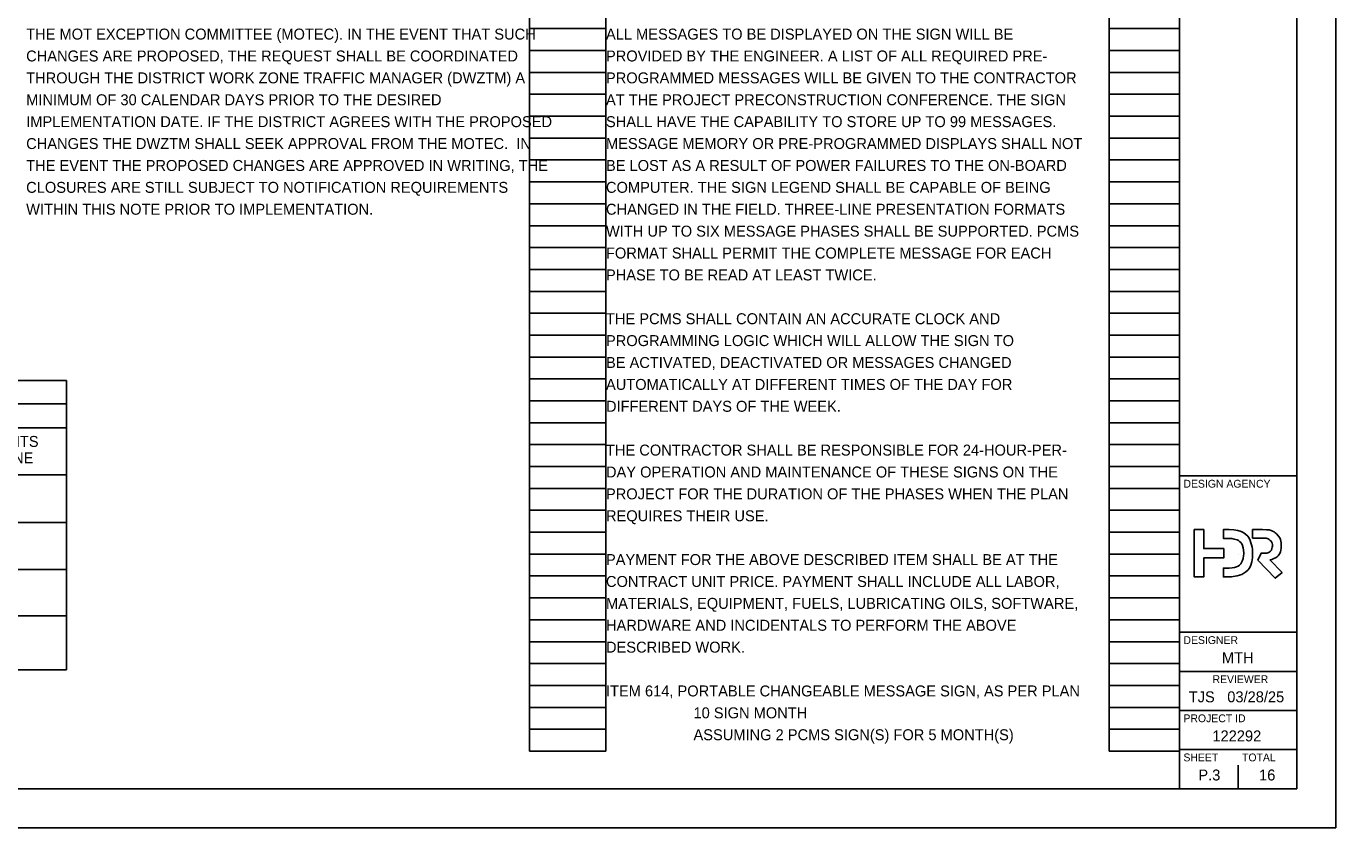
# Model space of a CAD drawing. Extents: x 0 to 49.3, y -31.9 to 22.
# Drawn here: x 17.24 to 34, y 0 to 10.25 of the extents above; entities that cross this region are included whole.
import ezdxf

# ---------------------------------------------------------------- set-up
doc = ezdxf.new("R2010")
doc.units = 0
for name, color, linetype in [('SH_Border', 7, 'Continuous'), ('SH_Cut_Line', 7, 'Continuous'), ('SH_Data', 7, 'Continuous'), ('SH_Text', 7, 'Continuous')]:
    doc.layers.add(name, color=color, linetype=linetype)

msp = doc.modelspace()

# ---------------------------------------------------------------- linework, layer by layer
at = {"layer": 'SH_Border'}
for p, q in [((32, 0.5), (32, 21.5)), ((32, 4.5), (33.5, 4.5)), ((32, 2.5), (33.5, 2.5)), ((32, 2), (33.5, 2)), ((32, 1.5), (33.5, 1.5)), ((32, 1), (33.5, 1))]:
    msp.add_line(p, q, dxfattribs=at)
msp.add_lwpolyline([(1.5, 21.5), (33.5, 21.5), (33.5, 0.5), (1.5, 0.5)], close=True, dxfattribs=at)
at = {"layer": 'SH_Cut_Line'}
msp.add_lwpolyline([(0, 0), (34, 0), (34, 22), (0, 22)], close=True, dxfattribs=at)
at = {"layer": 'SH_Data'}
for p, q in [((23.68, 0.98), (23.68, 21.14)), ((24.66, 0.98), (24.66, 21.14)), ((31.1, 0.98), (31.1, 21.14)), ((32, 0.98), (32, 21.14)), ((23.68, 10.22), (24.66, 10.22)), ((31.1, 10.22), (32, 10.22)), ((23.68, 9.94), (24.66, 9.94)), ((31.1, 9.94), (32, 9.94)), ((23.68, 9.66), (24.66, 9.66)), ((31.1, 9.66), (32, 9.66)), ((23.68, 9.38), (24.66, 9.38)), ((31.1, 9.38), (32, 9.38)), ((23.68, 9.1), (24.66, 9.1)), ((31.1, 9.1), (32, 9.1)), ((23.68, 8.82), (24.66, 8.82)), ((31.1, 8.82), (32, 8.82)), ((23.68, 8.54), (24.66, 8.54)), ((31.1, 8.54), (32, 8.54)), ((23.68, 8.26), (24.66, 8.26)), ((31.1, 8.26), (32, 8.26)), ((23.68, 7.98), (24.66, 7.98)), ((31.1, 7.98), (32, 7.98)), ((23.68, 7.7), (24.66, 7.7)), ((31.1, 7.7), (32, 7.7)), ((23.68, 7.42), (24.66, 7.42)), ((31.1, 7.42), (32, 7.42)), ((23.68, 7.14), (24.66, 7.14)), ((31.1, 7.14), (32, 7.14)), ((23.68, 6.86), (24.66, 6.86)), ((31.1, 6.86), (32, 6.86)), ((23.68, 6.58), (24.66, 6.58)), ((31.1, 6.58), (32, 6.58)), ((23.68, 6.3), (24.66, 6.3)), ((31.1, 6.3), (32, 6.3)), ((23.68, 6.02), (24.66, 6.02)), ((31.1, 6.02), (32, 6.02)), ((23.68, 5.74), (24.66, 5.74)), ((31.1, 5.74), (32, 5.74)), ((23.68, 5.46), (24.66, 5.46)), ((31.1, 5.46), (32, 5.46)), ((23.68, 5.18), (24.66, 5.18)), ((31.1, 5.18), (32, 5.18)), ((23.68, 4.9), (24.66, 4.9)), ((31.1, 4.9), (32, 4.9)), ((23.68, 4.62), (24.66, 4.62)), ((31.1, 4.62), (32, 4.62)), ((23.68, 4.34), (24.66, 4.34)), ((31.1, 4.34), (32, 4.34)), ((23.68, 4.06), (24.66, 4.06)), ((31.1, 4.06), (32, 4.06)), ((23.68, 3.78), (24.66, 3.78)), ((31.1, 3.78), (32, 3.78)), ((23.68, 3.5), (24.66, 3.5)), ((31.1, 3.5), (32, 3.5)), ((32.75, 3.5), (32.75, 3.5)), ((23.68, 3.22), (24.66, 3.22)), ((31.1, 3.22), (32, 3.22)), ((23.68, 2.94), (24.66, 2.94)), ((31.1, 2.94), (32, 2.94)), ((23.68, 2.66), (24.66, 2.66)), ((31.1, 2.66), (32, 2.66)), ((23.68, 2.38), (24.66, 2.38)), ((31.1, 2.38), (32, 2.38)), ((23.68, 2.1), (24.66, 2.1)), ((31.1, 2.1), (32, 2.1)), ((23.68, 1.82), (24.66, 1.82)), ((31.1, 1.82), (32, 1.82)), ((23.68, 1.54), (24.66, 1.54)), ((31.1, 1.54), (32, 1.54)), ((23.68, 1.26), (24.66, 1.26)), ((31.1, 1.26), (32, 1.26)), ((23.68, 0.98), (24.66, 0.98)), ((31.1, 0.98), (32, 0.98)), ((32.375, 0.675), (32.375, 0.675)), ((32.75, 0.5), (32.75, 0.8))]:
    msp.add_line(p, q, dxfattribs=at)
msp.add_lwpolyline([(32.565, 3.571), (32.311, 3.571), (32.311, 3.813), (32.189, 3.813), (32.189, 3.209), (32.311, 3.209), (32.311, 3.451), (32.565, 3.451)], close=True, dxfattribs=at)
for points in [[(32.634, 3.813), (32.562, 3.813), (32.562, 3.7), (32.634, 3.7)], [(33.063, 3.813), (32.935, 3.813), (32.935, 3.704), (33.072, 3.704)], [(32.936, 3.511), (32.936, 3.511), (32.936, 3.511), (32.936, 3.512), (32.936, 3.512)], [(33.077, 3.51), (33.043, 3.51), (33.003, 3.424), (33.226, 3.192), (33.313, 3.265), (33.155, 3.425)], [(32.634, 3.322), (32.562, 3.322), (32.562, 3.209), (32.634, 3.209)]]:
    msp.add_lwpolyline(points, dxfattribs=at)
for points in [[(32.936, 3.512), (32.936, 3.512), (32.935, 3.686), (32.808, 3.813), (32.634, 3.813)], [(32.634, 3.7), (32.634, 3.7), (32.744, 3.7), (32.822, 3.622), (32.822, 3.511)], [(33.239, 3.759), (33.239, 3.759), (33.193, 3.802), (33.141, 3.813), (33.063, 3.813)], [(33.072, 3.704), (33.072, 3.704), (33.113, 3.704), (33.141, 3.696), (33.161, 3.676)], [(33.302, 3.605), (33.302, 3.605), (33.302, 3.668), (33.284, 3.716), (33.239, 3.759)], [(33.189, 3.607), (33.189, 3.607), (33.189, 3.546), (33.136, 3.51), (33.077, 3.51)], [(33.155, 3.425), (33.155, 3.425), (33.242, 3.441), (33.302, 3.521), (33.302, 3.605)], [(33.161, 3.676), (33.161, 3.676), (33.179, 3.658), (33.189, 3.634), (33.189, 3.607)], [(32.822, 3.511), (32.822, 3.511), (32.822, 3.4), (32.744, 3.322), (32.634, 3.322)], [(32.634, 3.209), (32.634, 3.209), (32.808, 3.209), (32.935, 3.336), (32.936, 3.511)]]:
    msp.add_open_spline(points, degree=3, dxfattribs=at)
at = {"layer": 'SH_Text'}
for p, q in [((2.295, 5.721), (17.754, 5.721)), ((17.754, 5.721), (17.754, 2.02)), ((2.295, 5.421), (17.754, 5.421)), ((2.295, 5.114), (17.754, 5.114)), ((2.295, 4.513), (17.754, 4.513)), ((2.295, 3.902), (17.754, 3.902)), ((2.295, 3.302), (17.754, 3.302)), ((2.295, 2.712), (17.754, 2.712)), ((2.295, 2.02), (17.754, 2.02))]:
    msp.add_line(p, q, dxfattribs=at)

# ---------------------------------------------------------------- texts
at = {"layer": 'SH_Data'}
for s, height, p in [('DESIGN AGENCY', 0.1, (32.05, 4.35)), ('DESIGNER', 0.1, (32.05, 2.35)), ('MTH', 0.14, (32.542, 2.105)), ('REVIEWER', 0.1, (32.422, 1.85)), ('TJS', 0.14, (32.118, 1.605)), ('03/28/25', 0.14, (32.611, 1.605)), ('PROJECT ID', 0.1, (32.05, 1.35)), ('122292', 0.14, (32.421, 1.105)), ('SHEET', 0.1, (32.05, 0.85)), ('TOTAL', 0.1, (32.8, 0.85)), ('P.3', 0.14, (32.241, 0.605)), ('16', 0.14, (33.018, 0.605))]:
    msp.add_text(s, height=height, dxfattribs=at).set_placement(p)
at = {"layer": 'SH_Text'}
for s, p in [('THE MOT EXCEPTION COMMITTEE (MOTEC). IN THE EVENT THAT SUCH ', (17.24, 10.08)), ('ALL MESSAGES TO BE DISPLAYED ON THE SIGN WILL BE', (24.66, 10.08)), ('CHANGES ARE PROPOSED, THE REQUEST SHALL BE COORDINATED ', (17.24, 9.8)), ('PROVIDED BY THE ENGINEER. A LIST OF ALL REQUIRED PRE-', (24.66, 9.8)), ('THROUGH THE DISTRICT WORK ZONE TRAFFIC MANAGER (DWZTM) A ', (17.24, 9.52)), ('PROGRAMMED MESSAGES WILL BE GIVEN TO THE CONTRACTOR', (24.66, 9.52)), ('MINIMUM OF 30 CALENDAR DAYS PRIOR TO THE DESIRED ', (17.24, 9.24)), ('AT THE PROJECT PRECONSTRUCTION CONFERENCE. THE SIGN', (24.66, 9.24)), ('IMPLEMENTATION DATE. IF THE DISTRICT AGREES WITH THE PROPOSED ', (17.24, 8.96)), ('SHALL HAVE THE CAPABILITY TO STORE UP TO 99 MESSAGES.', (24.66, 8.96)), ('CHANGES THE DWZTM SHALL SEEK APPROVAL FROM THE MOTEC.  IN ', (17.24, 8.68)), ('MESSAGE MEMORY OR PRE-PROGRAMMED DISPLAYS SHALL NOT', (24.66, 8.68)), ('THE EVENT THE PROPOSED CHANGES ARE APPROVED IN WRITING, THE ', (17.24, 8.4)), ('BE LOST AS A RESULT OF POWER FAILURES TO THE ON-BOARD', (24.66, 8.4)), ('CLOSURES ARE STILL SUBJECT TO NOTIFICATION REQUIREMENTS ', (17.24, 8.12)), ('COMPUTER. THE SIGN LEGEND SHALL BE CAPABLE OF BEING', (24.66, 8.12)), ('WITHIN THIS NOTE PRIOR TO IMPLEMENTATION.', (17.24, 7.84)), ('CHANGED IN THE FIELD. THREE-LINE PRESENTATION FORMATS', (24.66, 7.84)), ('WITH UP TO SIX MESSAGE PHASES SHALL BE SUPPORTED. PCMS', (24.66, 7.56)), ('FORMAT SHALL PERMIT THE COMPLETE MESSAGE FOR EACH', (24.66, 7.28)), ('PHASE TO BE READ AT LEAST TWICE.', (24.66, 7)), ('THE PCMS SHALL CONTAIN AN ACCURATE CLOCK AND', (24.66, 6.44)), ('PROGRAMMING LOGIC WHICH WILL ALLOW THE SIGN TO', (24.66, 6.16)), ('BE ACTIVATED, DEACTIVATED OR MESSAGES CHANGED', (24.66, 5.88)), ('AUTOMATICALLY AT DIFFERENT TIMES OF THE DAY FOR', (24.66, 5.6)), ('DIFFERENT DAYS OF THE WEEK.', (24.66, 5.32)), ('DISINCENTIVE AMOUNTS', (15.1, 4.871)), ('THE CONTRACTOR SHALL BE RESPONSIBLE FOR 24-HOUR-PER-', (24.66, 4.76)), ('PER MINUTE PER LANE', (15.2, 4.661)), ('DAY OPERATION AND MAINTENANCE OF THESE SIGNS ON THE', (24.66, 4.48)), ('PROJECT FOR THE DURATION OF THE PHASES WHEN THE PLAN', (24.66, 4.2)), ('REQUIRES THEIR USE.', (24.66, 3.92)), ('PAYMENT FOR THE ABOVE DESCRIBED ITEM SHALL BE AT THE', (24.66, 3.36)), ('CONTRACT UNIT PRICE. PAYMENT SHALL INCLUDE ALL LABOR,', (24.66, 3.08)), ('MATERIALS, EQUIPMENT, FUELS, LUBRICATING OILS, SOFTWARE,', (24.66, 2.8)), ('HARDWARE AND INCIDENTALS TO PERFORM THE ABOVE', (24.66, 2.52)), ('DESCRIBED WORK.', (24.66, 2.24)), ('ITEM 614, PORTABLE CHANGEABLE MESSAGE SIGN, AS PER PLAN', (24.66, 1.68)), ('10 SIGN MONTH ', (25.78, 1.4)), ('ASSUMING 2 PCMS SIGN(S) FOR 5 MONTH(S)', (25.78, 1.12))]:
    msp.add_text(s, height=0.14, dxfattribs=at).set_placement(p)

doc.saveas('drawing.dxf')
